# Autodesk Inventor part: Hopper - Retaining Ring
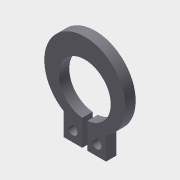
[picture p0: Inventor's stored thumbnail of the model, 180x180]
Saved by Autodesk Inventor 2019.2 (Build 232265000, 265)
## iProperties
Created: 2005-11
Part Number: Hopper - Retaining Ring
Document SubType Name: Modeling
Designer: floress
Material: Default
Density: 1 g/cm^3
Appearance: Steel
Author: floress
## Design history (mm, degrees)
sketch "Sketch1"
  geometry: L1 (-0.286, -1.465)-(-0.286, -1.592); L2 (-0.807, -2.308)-(-0.807, -2.859); L3 (-0.807, -2.859)-(-0.35, -2.859); L4 (-0.35, -2.859)-(-0.35, -2.224); L5 (0.234, -2.308)-(0.234, -2.859); L6 (0.234, -2.859)-(-0.223, -2.859); L7 (-0.223, -2.859)-(-0.223, -2.224); C1 r 0.113 at (-0.579, -2.597); C2 r 0.113 at (0.006, -2.597); A1 r 0.991 centre (-0.286, -1.465) between (0.234, -2.308) and (-0.807, -2.308); A2 r 0.635 centre (-0.286, -1.592) between (-0.223, -2.224) and (-0.35, -2.224); 1 further point
  constraints: 14 end point, 4 centre point, 4 point on circle, 4 symmetric about line, 1 coincident, 1 midpoint, 1 parallel, 1 vertical, 1 vertical alignment, 1 other
  dimensions: "d0" = 1.9812 diameter of A1; "d2" = 0.4572 distance of L2.end L3.end; "d3" = 0.127 diameter of L4 L1; "d4" = 1.27 diameter of A2; "d5" = 0.127 distance of L1.start L1.end
extrude "Extrusion1" new body sketch "Sketch1" distance "d7" = 0.254; taper "d8" = 0 deg
body "Solid1"
